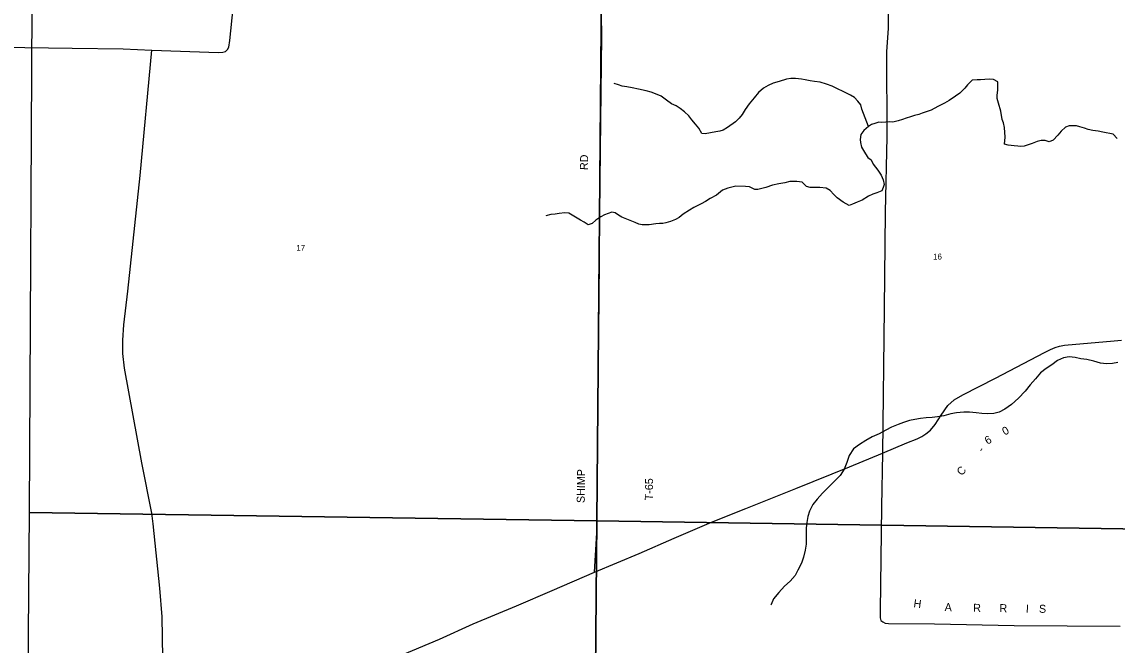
# Model space of a CAD drawing. Extents: x 1312308 to 1684953, y 460642 to 865172.
# Drawn here: x 1416487 to 1426746, y 592024 to 597865 of the extents above; entities that cross this region are included whole.
import ezdxf

# ---------------------------------------------------------------- set-up
doc = ezdxf.new("R2010")
doc.units = 0
for name, color, linetype in [('GM_X_County_Road', 7, 'Continuous'), ('GM_X_County_Road_Text', 7, 'Continuous'), ('GM_X_Minor_River', 7, 'Continuous'), ('GM_X_Section', 7, 'Continuous'), ('GM_X_Section_Text', 7, 'Continuous'), ('GM_X_Township_Road', 7, 'Continuous'), ('GM_X_Township_Road_Text', 7, 'Continuous')]:
    doc.layers.add(name, color=color, linetype=linetype)

msp = doc.modelspace()

# ---------------------------------------------------------------- linework, layer by layer
at = {"layer": 'GM_X_County_Road'}
for points in [[(1417811, 591710), (1417802, 592288), (1417780, 592558), (1417718, 593162), (1417704, 593261), (1417610, 593731), (1417449, 594621), (1417431, 594756), (1417432, 594883), (1417443, 595026), (1417480, 595341), (1417594, 596427), (1417704, 597600), (1418330, 597578), (1418369, 597580), (1418394, 597588), (1418414, 597606), (1418424, 597628), (1418435, 597690), (1418465, 597994)], [(1424549, 593823), (1424778, 593919), (1424872, 593956), (1424918, 593979), (1424956, 594003), (1424999, 594038), (1425041, 594092), (1425098, 594180), (1425161, 594269), (1425219, 594322), (1425300, 594370), (1425608, 594527), (1426066, 594765), (1426123, 594793), (1426165, 594813), (1426207, 594827), (1426252, 594835), (1426718, 594876), (1426788, 594883)], [(1420048, 591934), (1420399, 592081), (1420714, 592222), (1421120, 592392), (1421453, 592536), (1421852, 592708), (1422268, 592882), (1422597, 593026), (1422948, 593176), (1423269, 593305), (1423737, 593492), (1424241, 593696), (1424549, 593823)]]:
    msp.add_lwpolyline(points, dxfattribs=at)
at = {"layer": 'GM_X_Minor_River'}
for points in [[(1424416, 596884), (1424356, 597048), (1424345, 597087), (1424316, 597123), (1424287, 597158), (1424248, 597177), (1424185, 597211), (1424121, 597241), (1424078, 597262), (1424024, 597283), (1423965, 597299), (1423913, 597306), (1423871, 597312), (1423823, 597321), (1423791, 597328), (1423733, 597335), (1423691, 597336), (1423649, 597328), (1423580, 597307), (1423524, 597291), (1423477, 597270), (1423434, 597243), (1423387, 597204), (1423346, 597155), (1423300, 597097), (1423263, 597044), (1423233, 596998), (1423206, 596963), (1423173, 596930), (1423096, 596874), (1423055, 596851), (1423025, 596840), (1422988, 596835), (1422936, 596826), (1422886, 596817), (1422856, 596820), (1422827, 596869), (1422796, 596908), (1422763, 596947), (1422734, 596984), (1422693, 597021), (1422652, 597052), (1422615, 597077), (1422573, 597098), (1422524, 597132), (1422475, 597169), (1422439, 597184), (1422382, 597207), (1422334, 597219), (1422264, 597235), (1422203, 597246), (1422153, 597256), (1422111, 597263), (1422075, 597274), (1422036, 597289)], [(1426568, 596841), (1426518, 596848), (1426474, 596857), (1426440, 596870), (1426397, 596882), (1426365, 596890), (1426329, 596891), (1426297, 596890), (1426264, 596877), (1426221, 596840), (1426192, 596805), (1426147, 596758), (1426110, 596741), (1426071, 596752), (1426035, 596753), (1425996, 596744), (1425952, 596725), (1425875, 596701), (1425845, 596696), (1425815, 596701), (1425783, 596704), (1425727, 596711), (1425693, 596720), (1425697, 596786), (1425691, 596876), (1425683, 596919), (1425671, 596949), (1425658, 597027), (1425634, 597102), (1425623, 597147), (1425624, 597179), (1425629, 597226), (1425630, 597268), (1425629, 597303), (1425588, 597326), (1425550, 597327), (1425506, 597324), (1425468, 597321), (1425434, 597322), (1425389, 597319), (1425346, 597276), (1425321, 597245), (1425274, 597196), (1425231, 597169), (1425174, 597130), (1425129, 597104), (1425068, 597071), (1425003, 597039), (1424920, 597011), (1424888, 596996), (1424849, 596987), (1424811, 596974), (1424771, 596963), (1424736, 596950), (1424696, 596937), (1424645, 596926), (1424611, 596927), (1424579, 596926), (1424543, 596923), (1424513, 596924), (1424477, 596913), (1424446, 596902), (1424416, 596884), (1424375, 596846), (1424346, 596810), (1424340, 596764), (1424342, 596734), (1424352, 596692), (1424372, 596659), (1424389, 596627), (1424412, 596594), (1424441, 596573), (1424462, 596531), (1424505, 596476), (1424535, 596429), (1424556, 596384), (1424563, 596342), (1424556, 596312), (1424541, 596282), (1424497, 596262), (1424458, 596249), (1424418, 596232), (1424357, 596193), (1424310, 596174), (1424267, 596156), (1424235, 596144), (1424180, 596174), (1424125, 596215), (1424094, 596248), (1424057, 596285), (1424021, 596308), (1423961, 596314), (1423917, 596313), (1423871, 596312), (1423837, 596321), (1423796, 596364), (1423747, 596370), (1423680, 596368), (1423634, 596357), (1423578, 596346), (1423517, 596336)], [(1426748, 596772), (1426709, 596813), (1426677, 596820), (1426643, 596825), (1426614, 596832), (1426568, 596841)], [(1423517, 596336), (1423457, 596313), (1423382, 596293), (1423352, 596294), (1423304, 596318), (1423265, 596323), (1423176, 596325), (1423100, 596307), (1423051, 596288), (1422994, 596240), (1422935, 596211), (1422890, 596182), (1422849, 596160), (1422813, 596140), (1422782, 596127), (1422740, 596102), (1422682, 596062), (1422644, 596033), (1422609, 596014), (1422562, 595995), (1422520, 595982), (1422490, 595977), (1422460, 595974), (1422426, 595971), (1422363, 595964), (1422329, 595963), (1422297, 595962), (1422265, 595969), (1422232, 595984), (1422154, 596016), (1422107, 596035), (1422077, 596054), (1422044, 596077), (1422012, 596082), (1421945, 596056), (1421911, 596037), (1421862, 596006), (1421829, 595977), (1421790, 595962), (1421753, 595987), (1421721, 596006), (1421688, 596027), (1421656, 596045), (1421609, 596071), (1421573, 596074), (1421519, 596069), (1421483, 596064), (1421443, 596059), (1421396, 596048)], [(1426754, 594673), (1426703, 594662), (1426647, 594660), (1426591, 594667), (1426528, 594684), (1426464, 594700), (1426408, 594707), (1426352, 594720), (1426298, 594726), (1426244, 594715), (1426189, 594690), (1426134, 594651), (1426081, 594616), (1426028, 594575), (1425983, 594520), (1425933, 594463), (1425884, 594404), (1425822, 594337), (1425757, 594280), (1425696, 594234), (1425643, 594207), (1425593, 594194), (1425531, 594193), (1425479, 594196), (1425427, 594202), (1425363, 594207), (1425309, 594208), (1425242, 594200), (1425190, 594191), (1425124, 594174), (1425063, 594162), (1425013, 594157), (1424959, 594154), (1424906, 594147), (1424852, 594138), (1424800, 594128), (1424745, 594111), (1424695, 594092), (1424634, 594067), (1424579, 594038), (1424517, 594004), (1424452, 593975), (1424391, 593942), (1424332, 593905), (1424277, 593863)], [(1424277, 593863), (1424237, 593801), (1424214, 593734), (1424191, 593674), (1424151, 593615), (1424094, 593554), (1424036, 593499), (1423987, 593448), (1423938, 593393), (1423897, 593341), (1423865, 593280), (1423850, 593228), (1423839, 593174), (1423834, 593120), (1423833, 593024), (1423834, 592970), (1423825, 592914), (1423809, 592848), (1423790, 592792), (1423757, 592727), (1423729, 592675), (1423684, 592624), (1423629, 592575), (1423576, 592518), (1423528, 592457), (1423507, 592403), (1423503, 592399)]]:
    msp.add_lwpolyline(points, dxfattribs=at)
at = {"layer": 'GM_X_Section'}
for points in [[(1416586, 598599), (1421918, 598528), (1421873, 593189), (1416559, 593267)], [(1421918, 598528), (1427279, 598407), (1427213, 593108), (1421873, 593189)], [(1416559, 593267), (1421873, 593189), (1421827, 587888), (1416514, 587948)], [(1421873, 593189), (1427213, 593108), (1427165, 587821), (1421827, 587888)]]:
    msp.add_lwpolyline(points, close=True, dxfattribs=at)
at = {"layer": 'GM_X_Township_Road'}
for points in [[(1424690, 604458), (1424690, 604458), (1424686, 604094), (1424660, 602408), (1424656, 601939), (1424654, 601648), (1424641, 600564), (1424629, 599771), (1424622, 598918), (1424603, 597924), (1424602, 597802), (1424587, 597587), (1424590, 596789), (1424574, 596082), (1424564, 595180), (1424549, 593823)], [(1421852, 592708), (1421872, 593077), (1421879, 593903), (1421888, 594760), (1421893, 595245), (1421901, 596086), (1421911, 596940), (1421920, 597729), (1421912, 598140), (1421916, 598655), (1421932, 599256)], [(1413954, 597420), (1414179, 597515), (1414261, 597552), (1414396, 597611), (1414489, 597652), (1414532, 597666), (1414581, 597670), (1414700, 597664), (1415104, 597648), (1415487, 597635), (1416067, 597633), (1416958, 597619), (1417434, 597612), (1417704, 597600)], [(1424549, 593823), (1424540, 593324), (1424527, 592344), (1424526, 592306)], [(1424526, 592306), (1424526, 592278), (1424534, 592254), (1424552, 592241), (1424573, 592229), (1424604, 592226), (1425036, 592222), (1425783, 592208), (1426277, 592203), (1426774, 592200)]]:
    msp.add_lwpolyline(points, dxfattribs=at)

# ---------------------------------------------------------------- texts
at = {"layer": 'GM_X_County_Road_Text'}
for s, rotation, p in [('0', 27.3633, (1425693, 593987)), ('6', 27.7974, (1425530, 593901)), ('-', 55.772, (1425489, 593825)), ('C', 47.0634, (1425290, 593606))]:
    msp.add_text(s, height=75, rotation=rotation, dxfattribs=at).set_placement(p)
at = {"layer": 'GM_X_Section_Text'}
for s, p in [('17', (1419058, 595720)), ('16', (1425023, 595638))]:
    msp.add_text(s, height=55.3, rotation=0, dxfattribs=at).set_placement(p)
at = {"layer": 'GM_X_Township_Road_Text'}
for s, rotation, p in [('RD', 89.0128, (1421789, 596476)), ('SHIMP', 89.3285, (1421759, 593355)), ('T-65', 89.2949, (1422397, 593381)), ('H', 352.7645, (1424836, 592379)), ('A', 358.5278, (1425130, 592343)), ('R', 359.1768, (1425398, 592336)), ('R', 359.1725, (1425644, 592333)), ('I', 359.1739, (1425891, 592329)), ('S', 359.1732, (1426014, 592327))]:
    msp.add_text(s, height=75, rotation=rotation, dxfattribs=at).set_placement(p)

doc.saveas('drawing.dxf')
